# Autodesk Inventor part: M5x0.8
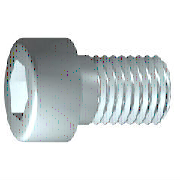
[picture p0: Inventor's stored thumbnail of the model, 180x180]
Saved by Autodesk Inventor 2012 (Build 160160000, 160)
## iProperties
IsCustomPart: 0
Manager: KYOUNG IL JANG
Company: 한국ATC센터
Created: 2009-02
Part Number: M5x0.8
Material: Steel, Mild
Description: 6각머리 태핑 나사
Document SubType Name: Modeling
Standard: KS B 1003
Standards Organization: KS
Language: ko-KR
Size Designation: M 5 x 20
Categories: <MemberInstance><Categories><Category DisplayName="조임쇠" InternalName="e4da775c-781d-43d5-af7c-5136215cf5a6" Mnemonic="FSTN"><Category DisplayName="볼트" InternalN
Density: 1 g/cm^3
Checked By: KYOUNG IL JANG
Vendor: CBT Solutions
Designer: KYOUNG IL JANG
Author: KYOUNG IL JANG
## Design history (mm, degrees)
body "Solid1"
workplane "Work Plane1"
fillet "Fillet2" dims "d30" = 0.1 (= R)
revolve "본체" stored, may be unused: angle "d10" = 90 deg
sketch "스케치2"
  geometry: L1 (0, -5.95)-(0, 5.95) reference; L2 (-5.95, 0)-(5.95, 0) reference; L3 (2.309, 0)-(1.155, -2); L4 (1.155, -2)-(-1.155, -2); L5 (-1.155, -2)-(-2.309, 0); L6 (-2.309, 0)-(-1.155, 2); L7 (-1.155, 2)-(1.155, 2); L8 (1.155, 2)-(2.309, 0); 2 further points
  constraints: 12 end point, 1 coincident, 1 horizontal alignment, 1 point on line, 12 other
extrude "슬롯" join sketch "스케치2" stored distance "d11" = 10; taper "d12" = 0 deg
fillet "모깎기1" dims "d17" = 0.5 (= RR)
feature "스레드" dims "d13" = 18 (= GEL), "d14" = 0
chamfer "모따기1" distance "d15" = 0.49076 (= -0.5 x SPD + 0.5 x GD); stored, may be unused: second distance "d16" = 0.49076 (= GUL), angle "d27" = 45 deg
sketch "스케치1"
  geometry: L1 (-1.167, 0)-(20, 0); L2 (20, 0)-(20, 2.5); L3 (20, 2.5)-(2, 2.5); L4 (2, 2.5)-(1.509, 2.5); L5 (1.509, 2.5)-(0, 2.5); L6 (0, 2.5)-(0, 4.25); L7 (0, 4.25)-(-5, 4.25); L8 (-5, 4.25)-(-5, 2.309); L9 (-5, 2.309)-(-2.5, 2.309); L10 (-2.5, 2.309)-(-1.167, 0); L11 (-10, 0)-(25, 0) reference; L12 (0, -0.85)-(0, 5.1) reference; L13 (2, 2.5)-(0, 2.5)
  constraints: 22 end point, 6 parallel, 2 collinear, 2 perpendicular, 1 horizontal, 1 point on line
  dimensions: "d1" = 18 distance from line of L3.end L2 (= GEL); "d2" = 0.49086 distance of L4.end L3.end (computed from GAL); "d3" = 5 distance between parallel lines of L8 L6 (= KOH); "d4" = 2.5 distance of L8.end L9.end (= INTI); "d5" = 60 deg angle of L10 L1; "d6" = 5 diameter of L3 L1 (= GD); "d7" = 5 diameter of L5 L1 (= BDM); "d8" = 4.6188 diameter of L9 L1 (= 1.1547 x SW); "d9" = 8.5 diameter of L7 L1 (= KOD); "d26" = 20 distance between parallel lines of L12 L2 (= NLG)
other parameters: "GD" = 5 (= NND) [user parameter; used in 2 equation terms], "NLG" = 20 [user parameter; used in 1 equation term], "GEL" = 18 [user parameter; used in 2 equation terms], "KOD" = 8.5 [user parameter; used in 1 equation term], "KOH" = 5 [user parameter; used in 1 equation term], "INTI" = 2.5 [user parameter; used in 1 equation term], "GAL" = 0.49076 (= 0.61345 x PTC) [user parameter; used in 1 equation term], "GUL" = 0.49076 (= 0.61345 x PTC) [user parameter; used in 1 equation term], "BDM" = 5 (= NND) [user parameter; used in 1 equation term], "SW" = 4 [user parameter; used in 2 equation terms], "RR" = 0.5 [user parameter; used in 1 equation term], "SPD" = 4.01848 (= NND - 1.2269 x PTC) [user parameter; used in 1 equation term], "d19" = 0, "d28" = 0, "d29" = 0, "R" = 0.1 [user parameter; used in 1 equation term], "PHH" = 0.2 [user parameter], "GD1" = 4.01848 (= THREADDIA - 1.2269 x PTC) [user parameter], "THREADDIA" = 5 [user parameter; used in 1 equation term], "FAWI" = 45 deg [user parameter], "TPU" = 12.5 (computed from PTC) [user parameter], "PTC" = 0.8 [user parameter; used in 5 equation terms], "NND" = 5 [user parameter; used in 3 equation terms], "TOA" = 30 deg [user parameter], "E0" = 4.62 (= 1.155 x SW) [user parameter]
